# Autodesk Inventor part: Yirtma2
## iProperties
Created: 2008-12
Part Number: Yirtma2
Material: Default
Document SubType Name: Sheet Metal
Designer: Designer
Density: 1 g/cm^3
Sheet Metal Rule: Default_mm
Author: Designer
